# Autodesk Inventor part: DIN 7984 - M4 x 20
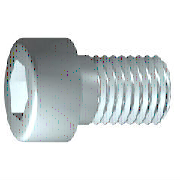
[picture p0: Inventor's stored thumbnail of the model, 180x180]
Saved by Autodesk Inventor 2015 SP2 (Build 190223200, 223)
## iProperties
IsCustomPart: 0
Created: 2012-02
Part Number: DIN 7984 - M4 x 20
Material: Stahl, weich
Description: Zylinderkopfschraube
Document SubType Name: Modeling
Standard: DIN 7984
Designer: Ente
Standard Revision: 1985
Standards Organization: DIN
Language: de-DE
Size Designation: M4 x 20
Categories: <MemberInstance><Categories><Category DisplayName="Verbindungselemente" InternalName="e4da775c-781d-43d5-af7c-5136215cf5a6" Mnemonic="FSTN"><Category DisplayNam
Density: 7.85 g/cm^3
Appearance: Halbpoliert
Author: Ente
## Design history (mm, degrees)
sketch "Skizze1"
  geometry: L1 (0.333, 0)-(20, 0); L2 (20, 0)-(20, 2); L3 (20, 2)-(2.1, 2); L4 (2.1, 2)-(1.67, 2); L5 (1.67, 2)-(0, 2); L6 (0, 2)-(0, 3.5); L7 (0, 3.5)-(-2.8, 3.5); L8 (-2.8, 3.5)-(-2.8, 1.443); L9 (-2.8, 1.443)-(-0.5, 1.443); L10 (-0.5, 1.443)-(0.333, 0); L11 (-7.36, 0)-(24.56, 0) reference; L12 (0, -0.7)-(0, 4.2) reference; L13 (2.1, 2)-(0, 2)
  constraints: 22 end point, 6 parallel, 2 collinear, 2 perpendicular, 1 horizontal, 1 point on line
  dimensions: "d1" = 17.9 distance from line of L3.end L2 (= GEL); "d2" = 0.42952 distance of L4.end L3.end (computed from GAL); "d3" = 2.8 distance between parallel lines of L8 L6 (= KOH); "d4" = 2.3 distance of L8.end L9.end (= INTI); "d5" = 60 deg angle of L10 L1; "d6" = 4 diameter of L3 L1 (= GD); "d7" = 4 diameter of L5 L1 (= BDM); "d8" = 2.88675 diameter of L9 L1 (= 1.1547 x SW); "d9" = 7 diameter of L7 L1 (= KOD); "d26" = 20 distance between parallel lines of L12 L2 (= NLG)
revolve "Körper" sketch "Skizze1" stored, may be unused: angle "d10" = 90 deg
sketch "Skizze2"
  geometry: L1 (0, -4.9)-(0, 4.9) reference; L2 (-4.9, 0)-(4.9, 0) reference; L3 (1.443, 0)-(0.722, -1.25); L4 (0.722, -1.25)-(-0.722, -1.25); L5 (-0.722, -1.25)-(-1.443, 0); L6 (-1.443, 0)-(-0.722, 1.25); L7 (-0.722, 1.25)-(0.722, 1.25); L8 (0.722, 1.25)-(1.443, 0); 2 further points
  constraints: 12 end point, 1 coincident, 1 horizontal alignment, 1 point on line, 12 other
extrude "Loch" join sketch "Skizze2" stored distance "d11" = 10; taper "d12" = 0 deg
workplane "Work Plane1"
fillet "Fillet2" dims "d30" = 0.1 (= R)
body "Solid1"
fillet "Rundung1" dims "d17" = 0.4 (= RR)
feature "Gewinde" dims "d13" = 17.9 (= GEL), "d14" = 0
chamfer "Fase1" distance "d15" = 0.42941 (= -0.5 x SPD + 0.5 x GD); stored, may be unused: second distance "d16" = 0.42941 (= GUL), angle "d27" = 45 deg
other parameters: "GD" = 4 (= NND) [user parameter; used in 2 equation terms], "NLG" = 20 [user parameter; used in 1 equation term], "GEL" = 17.9 [user parameter; used in 2 equation terms], "KOD" = 7 [user parameter; used in 1 equation term], "KOH" = 2.8 [user parameter; used in 1 equation term], "INTI" = 2.3 [user parameter; used in 1 equation term], "GAL" = 0.42941 (= 0.61345 x PTC) [user parameter; used in 1 equation term], "GUL" = 0.42941 (= 0.61345 x PTC) [user parameter; used in 1 equation term], "BDM" = 4 (= NND) [user parameter; used in 1 equation term], "SW" = 2.5 [user parameter; used in 2 equation terms], "RR" = 0.4 [user parameter; used in 1 equation term], "SPD" = 3.14117 (= NND - 1.2269 x PTC) [user parameter; used in 1 equation term], "d19" = 0, "d28" = 0, "d29" = 0, "R" = 0.1 [user parameter; used in 1 equation term], "TOA" = 30 deg [user parameter], "GD1" = 3.14117 (= THREADDIA - 1.2269 x PTC) [user parameter], "THREADDIA" = 4 [user parameter; used in 1 equation term], "FAWI" = 45 deg [user parameter], "ANG" = 120 deg [user parameter], "TPU" = 14.28571 (computed from PTC) [user parameter], "PTC" = 0.7 [user parameter; used in 5 equation terms], "NND" = 4 [user parameter; used in 3 equation terms], "E0" = 2.8875 (= 1.155 x SW) [user parameter]
